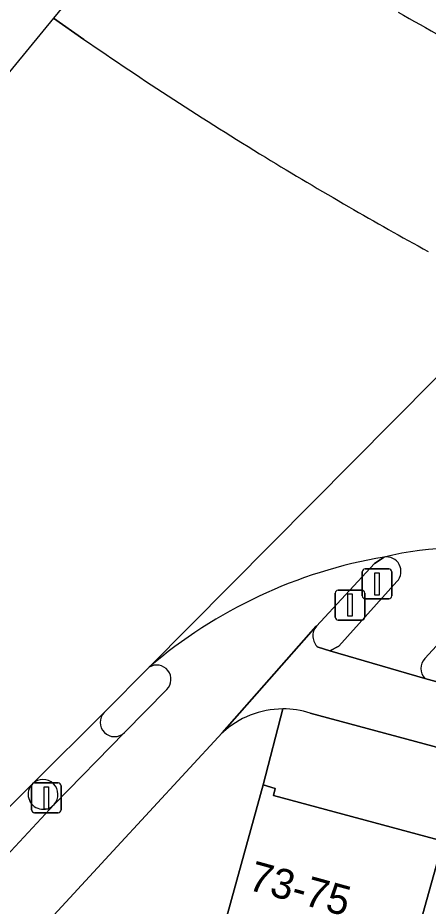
# Model space of a CAD drawing. Extents: x 160675 to 161153, y 383241 to 383714.
# Drawn here: x 160731.76 to 160745.48, y 383593.67 to 383623.39 of the extents above; entities that cross this region are included whole.
import ezdxf

# ---------------------------------------------------------------- set-up
doc = ezdxf.new("R2010")
doc.units = 0
for name, color, linetype in [('IMGEO_Drukknoppaal', 7, 'Continuous'), ('IMGEO_Fietspad_gesloten', 7, 'Continuous'), ('IMGEO_Fietspad_open', 7, 'Continuous'), ('IMGEO_OVBaan_gesloten', 7, 'Continuous'), ('IMGEO_Pand', 7, 'Continuous'), ('IMGEO_Pand_nummerreeks', 7, 'Continuous'), ('IMGEO_Rijbaan_lokaal_gesloten', 7, 'Continuous'), ('IMGEO_Verkeerseiland_open', 7, 'Continuous'), ('IMGEO_Verkeersregelinstallatiepaal', 7, 'Continuous'), ('IMGEO_Voetpad_open', 7, 'Continuous')]:
    doc.layers.add(name, color=color, linetype=linetype)

msp = doc.modelspace()

# ---------------------------------------------------------------- linework, layer by layer
at = {"layer": 'IMGEO_Drukknoppaal'}
for p, q in [((160742.473, 383604.24), (160743.263, 383604.24)), ((160743.263, 383604.24), (160742.473, 383604.24)), ((160742.373, 383603.34), (160742.373, 383604.14)), ((160742.373, 383604.14), (160742.373, 383603.34)), ((160743.363, 383604.14), (160743.363, 383603.34)), ((160743.363, 383603.34), (160743.363, 383604.14)), ((160743.263, 383603.24), (160742.473, 383603.24)), ((160742.473, 383603.24), (160743.263, 383603.24))]:
    msp.add_line(p, q, dxfattribs=at)
msp.add_lwpolyline([(160742.793, 383604.115), (160742.943, 383604.115), (160742.943, 383603.365), (160742.793, 383603.365), (160742.793, 383604.115)], dxfattribs=at)
for centre, start, end in [((160742.473, 383604.14), 90, 180), ((160742.473, 383604.14), 90, 180), ((160743.263, 383604.14), 0, 90), ((160743.263, 383604.14), 360, 90), ((160742.473, 383603.34), 180, 270), ((160742.473, 383603.34), 180, 270), ((160743.263, 383603.34), 270, 0), ((160743.263, 383603.34), 270, 0)]:
    msp.add_arc(centre, 0.1, start, end, dxfattribs=at)
at = {"layer": 'IMGEO_Fietspad_gesloten'}
for points in [[(160734.953, 383595.515), (160738.597, 383599.464), (160741.736, 383603.037), (160741.752, 383603.04), (160743.691, 383605.136), (160744.009, 383605.349)], [(160741.752, 383603.04), (160741.736, 383603.037), (160738.597, 383599.464)], [(160754.374, 383598.874), (160753.356, 383599.164), (160746.358, 383601.021), (160745.375, 383601.284), (160742.198, 383602.214), (160741.8, 383602.33)], [(160736.741, 383600.914), (160735.326, 383599.476), (160732.973, 383597.065), (160730.642, 383594.571), (160720.241, 383583.296)], [(160741.54, 383600.127), (160851.652, 383570.489), (160869.912, 383565.633), (160904.417, 383556.04)], [(160720.294, 383579.626), (160734.953, 383595.515)]]:
    msp.add_lwpolyline(points, dxfattribs=at)
for centre, radius, start, end in [((160746.732, 383589.326), 16.253, 99.6442, 130.6224), ((160742.128, 383602.709), 0.501, 138.6051, 229.1302), ((160736.405, 383601.256), 0.479, 314.5312, 122.0938), ((160740.636, 383597.272), 2.994, 90.3506, 132.939), ((160740.642, 383597.298), 2.969, 72.391, 90.4624)]:
    msp.add_arc(centre, radius, start, end, dxfattribs=at)
at = {"layer": 'IMGEO_Fietspad_open'}
for points in [[(160734.651, 383600.15), (160732.251, 383597.762)], [(160732.973, 383597.065), (160735.326, 383599.476)]]:
    msp.add_lwpolyline(points, dxfattribs=at)
for centre, radius, start, end in [((160734.991, 383599.816), 0.477, 135.4688, 314.6162), ((160732.602, 383597.403), 0.502, 317.6483, 134.3703)]:
    msp.add_arc(centre, radius, start, end, dxfattribs=at)
at = {"layer": 'IMGEO_OVBaan_gesloten'}
for points in [[(160736.997, 383628.299), (160733.951, 383624.587), (160732.957, 383623.376)], [(160732.957, 383623.376), (160733.973, 383622.667)]]:
    msp.add_lwpolyline(points, dxfattribs=at)
for centre, radius, start, end in [((160791.624, 383706.242), 95.163, 240.30172, 242.33665), ((160810.022, 383733.071), 134.062, 235.44014, 238.53271), ((160806.621, 383727.566), 127.591, 238.54501, 240.00045), ((160806.414, 383726.83), 126.85, 239.91514, 241.29367)]:
    msp.add_arc(centre, radius, start, end, dxfattribs=at)
at = {"layer": 'IMGEO_Pand'}
for points in [[(160745.98, 383595.844), (160740.309, 383597.372), (160740.363, 383597.607), (160739.966, 383597.73), (160739, 383594.22), (160735.987, 383583.276), (160739.286, 383582.381), (160739.571, 383583.729), (160742.385, 383582.972)], [(160745.98, 383595.844), (160742.385, 383582.972), (160748.468, 383581.333), (160752.064, 383594.206)]]:
    msp.add_lwpolyline(points, close=True, dxfattribs=at)
at = {"layer": 'IMGEO_Rijbaan_lokaal_gesloten'}
for points in [[(160733.973, 383622.667), (160732.957, 383623.376), (160717.907, 383605.036)], [(160727.222, 383611.055), (160724.798, 383608.11), (160722.601, 383605.517), (160720.463, 383602.931), (160723.044, 383600.836), (160725.485, 383598.855), (160727.682, 383597.073), (160729.825, 383595.333), (160732.251, 383597.762), (160734.651, 383600.15), (160736.15, 383601.662), (160747.056, 383612.661), (160746.79, 383612.921)], [(160747.056, 383612.661), (160736.15, 383601.662)]]:
    msp.add_lwpolyline(points, dxfattribs=at)
for centre, radius, start, end in [((160791.624, 383706.242), 95.163, 240.30172, 242.33665), ((160810.022, 383733.071), 134.062, 235.44014, 238.53271), ((160806.621, 383727.566), 127.591, 238.54501, 240.00045), ((160806.414, 383726.83), 126.85, 239.91514, 241.29367), ((160746.577, 383594.604), 11.048, 78.5299, 103.4419), ((160746.732, 383589.326), 16.253, 99.6442, 130.6224)]:
    msp.add_arc(centre, radius, start, end, dxfattribs=at)
at = {"layer": 'IMGEO_Verkeerseiland_open'}
for points in [[(160744.009, 383605.349), (160743.691, 383605.136), (160741.752, 383603.04)], [(160748.371, 383605.24), (160747.562, 383604.331), (160745.368, 383601.95)], [(160741.8, 383602.33), (160742.198, 383602.214), (160742.496, 383602.372), (160744.438, 383604.531)], [(160736.15, 383601.662), (160734.651, 383600.15)], [(160745.375, 383601.284), (160746.358, 383601.021)], [(160735.326, 383599.476), (160736.741, 383600.914)]]:
    msp.add_lwpolyline(points, dxfattribs=at)
for centre, radius, start, end in [((160744.088, 383604.869), 0.486, 315.9771, 99.3724), ((160742.128, 383602.709), 0.501, 138.6051, 229.1302), ((160745.727, 383601.621), 0.487, 137.5057, 223.6987), ((160736.405, 383601.256), 0.479, 314.5312, 122.0938), ((160734.991, 383599.816), 0.477, 135.4688, 314.6162), ((160732.609, 383597.41), 0.502, 135.447, 316.5717), ((160732.602, 383597.403), 0.502, 317.6483, 134.3703)]:
    msp.add_arc(centre, radius, start, end, dxfattribs=at)
at = {"layer": 'IMGEO_Verkeersregelinstallatiepaal'}
for p, q in [((160743.275, 383604.049), (160743.275, 383604.849)), ((160743.275, 383604.849), (160743.275, 383604.049)), ((160743.375, 383604.949), (160744.165, 383604.949)), ((160744.165, 383604.949), (160743.375, 383604.949)), ((160744.265, 383604.849), (160744.265, 383604.049)), ((160744.265, 383604.049), (160744.265, 383604.849)), ((160744.165, 383603.949), (160743.375, 383603.949)), ((160743.375, 383603.949), (160744.165, 383603.949)), ((160732.22, 383596.891), (160732.22, 383597.691)), ((160732.22, 383597.691), (160732.22, 383596.891)), ((160732.32, 383597.791), (160733.11, 383597.791)), ((160733.11, 383597.791), (160732.32, 383597.791)), ((160733.21, 383597.691), (160733.21, 383596.891)), ((160733.21, 383596.891), (160733.21, 383597.691)), ((160733.11, 383596.791), (160732.32, 383596.791)), ((160732.32, 383596.791), (160733.11, 383596.791))]:
    msp.add_line(p, q, dxfattribs=at)
for points in [[(160743.695, 383604.824), (160743.845, 383604.824), (160743.845, 383604.074), (160743.695, 383604.074), (160743.695, 383604.824)], [(160732.64, 383597.666), (160732.79, 383597.666), (160732.79, 383596.916), (160732.64, 383596.916), (160732.64, 383597.666)]]:
    msp.add_lwpolyline(points, dxfattribs=at)
for centre, start, end in [((160743.375, 383604.849), 90, 180), ((160743.375, 383604.849), 90, 180), ((160744.165, 383604.849), 0, 90), ((160744.165, 383604.849), 360, 90), ((160743.375, 383604.049), 180, 270), ((160743.375, 383604.049), 180, 270), ((160744.165, 383604.049), 270, 0), ((160744.165, 383604.049), 270, 0), ((160732.32, 383597.691), 90, 180), ((160732.32, 383597.691), 90, 180), ((160733.11, 383597.691), 0, 90), ((160733.11, 383597.691), 360, 90), ((160732.32, 383596.891), 180, 270), ((160732.32, 383596.891), 180, 270), ((160733.11, 383596.891), 270, 0), ((160733.11, 383596.891), 270, 0)]:
    msp.add_arc(centre, 0.1, start, end, dxfattribs=at)
at = {"layer": 'IMGEO_Voetpad_open'}
for points in [[(160745.368, 383601.95), (160747.562, 383604.331), (160748.371, 383605.24)], [(160744.438, 383604.531), (160742.496, 383602.372), (160742.198, 383602.214), (160745.375, 383601.284)], [(160739, 383594.22), (160739.966, 383597.73), (160740.618, 383600.266)], [(160740.618, 383600.266), (160739.966, 383597.73), (160740.363, 383597.607), (160740.309, 383597.372), (160745.98, 383595.844), (160752.064, 383594.206), (160758.147, 383592.567), (160764.231, 383590.928), (160770.314, 383589.29), (160776.398, 383587.651), (160782.481, 383586.013), (160788.565, 383584.374), (160794.648, 383582.735), (160800.731, 383581.097), (160806.815, 383579.458), (160812.898, 383577.819), (160818.982, 383576.181), (160825.065, 383574.542)], [(160851.652, 383570.489), (160741.54, 383600.127)], [(160738.597, 383599.464), (160734.953, 383595.515), (160720.294, 383579.626)], [(160732.251, 383597.762), (160729.825, 383595.333)], [(160730.642, 383594.571), (160732.973, 383597.065)], [(160726.9, 383575.565), (160735.379, 383573.223), (160736.61, 383572.879), (160736.736, 383573.058), (160738.356, 383578.98), (160739.286, 383582.381), (160735.987, 383583.276), (160739, 383594.22)]]:
    msp.add_lwpolyline(points, dxfattribs=at)
for centre, radius, start, end in [((160746.577, 383594.604), 11.048, 78.5299, 103.4419), ((160744.088, 383604.869), 0.486, 315.9771, 99.3724), ((160745.727, 383601.621), 0.487, 137.5057, 223.6987), ((160740.636, 383597.272), 2.994, 90.3506, 132.939), ((160740.642, 383597.298), 2.969, 72.391, 90.4624), ((160732.609, 383597.41), 0.502, 135.447, 316.5717)]:
    msp.add_arc(centre, radius, start, end, dxfattribs=at)

# ---------------------------------------------------------------- texts
at = {"layer": 'IMGEO_Pand_nummerreeks'}
msp.add_text('73-75', height=1, rotation=344.6045, dxfattribs=at).set_placement((160739.42, 383594.232))

doc.saveas('drawing.dxf')
